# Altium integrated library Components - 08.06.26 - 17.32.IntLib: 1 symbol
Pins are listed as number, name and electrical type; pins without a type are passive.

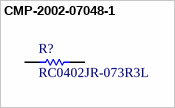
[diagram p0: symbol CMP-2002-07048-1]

## CMP-2002-07048-1
designator R?, comment RC0402JR-073R3L
Manufacturer: Yageo / Phycomp
footprint RESC1005X40X25ML05T10 (Chip Resistor, 2-Leads, Body 1.00x0.50mm, IPC Low Density)
footprint RESC1005X40X25LL05T10 (Chip Resistor, 2-Leads, Body 1.00x0.50mm, IPC High Density)
footprint RESC1005X40X25NL05T10 (Chip Resistor, 2-Leads, Body 1.00x0.50mm, IPC Medium Density)
pins: 1, 2
1 alternate drawing of the same symbol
